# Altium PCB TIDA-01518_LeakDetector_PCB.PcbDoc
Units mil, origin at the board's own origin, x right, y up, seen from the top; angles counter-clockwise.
Board outline 3400 x 1900 mil, 2 copper layers (Top Layer, Bottom Layer), stack 40 mil thick; 53 components, 50 nets, 126 pads, 102 vias.
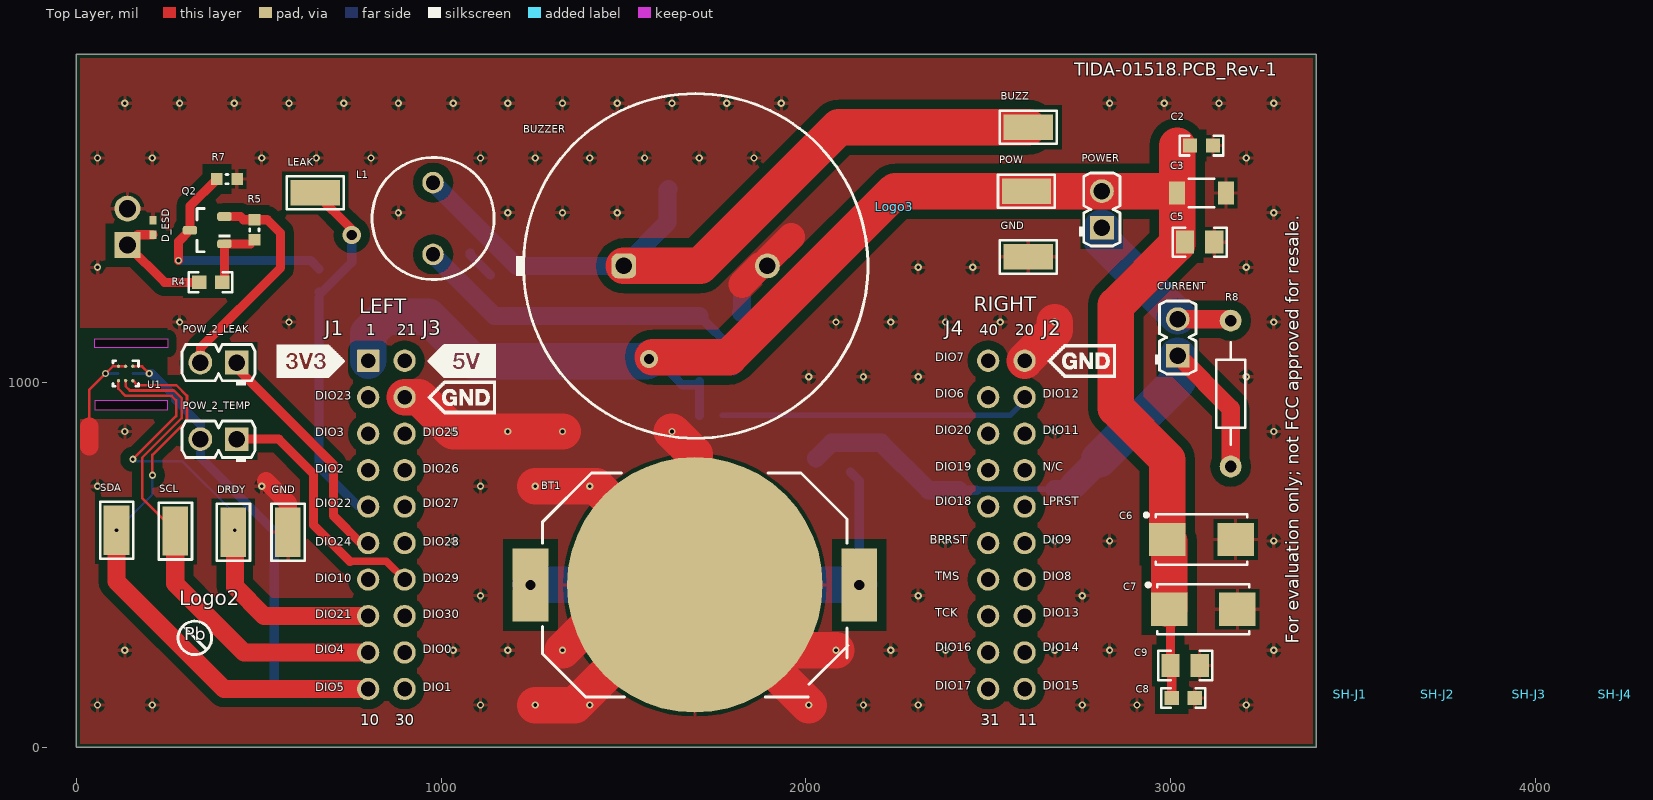
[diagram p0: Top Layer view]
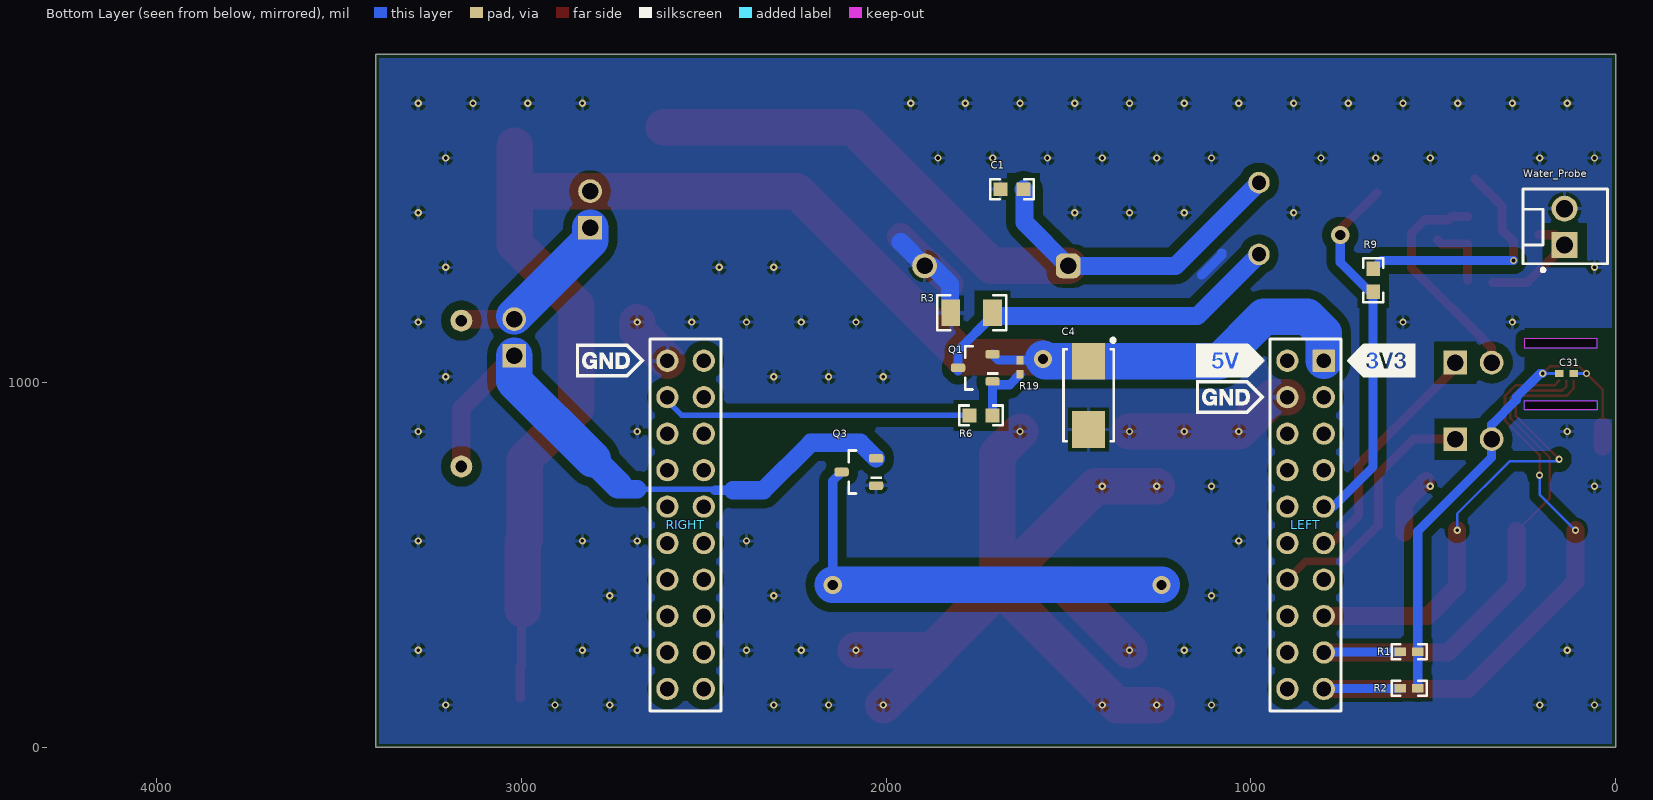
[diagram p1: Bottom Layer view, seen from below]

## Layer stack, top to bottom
Top Solder: solder mask 0.4, Solder Resist, Dk 3.5
Top Layer: signal copper 1.4
Dielectric1: core 37.2, FR-4, Dk 4.8
Bottom Layer: signal copper 1.4
Bottom Solder: solder mask 0.4, Solder Resist, Dk 3.5

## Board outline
0,0 3400,0 3400,1900 0,1900
cut-out: 50,950 50,925 250,925 250,950
cut-out: 50,1095 50,1120 250,1120 250,1095

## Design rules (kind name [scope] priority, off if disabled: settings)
AcuteAngle [All] p1: minimum=4.50000000000000E+0001 checktracksonly=FALSE
AssemblyTestPointUsage [All] p1: valid=2
BoardOutlineClearance BoardOutlineClearance_MountingHoles [OnCopper and InComponentClass('Mounting Holes')] p1: gap=10 ignorepadtopadclearanceinfootprint=FALSE
BoardOutlineClearance BoardOutlineClearance_Poly [OnCopper and IsPoly] p2: gap=10 ignorepadtopadclearanceinfootprint=FALSE
BoardOutlineClearance [OnCopper and Not InComponentClass('Logo') and not InComponentClass('FiducialMark') and not InRegion(1000,500,4000,800) and not InPoly] p3: gap=10 ignorepadtopadclearanceinfootprint=FALSE
Clearance Clearance_Keepouts [((IsTrack Or IsArc) And Not InPoly) And IsFree and IsKeepOut vs ((IsTrack Or IsArc) And Not InPoly) And IsFree and IsKeepOut] p1: gap=0 ignorepadtopadclearanceinfootprint=FALSE
Clearance Clearance_Poly [InPolygon] p2: gap=25 ignorepadtopadclearanceinfootprint=FALSE except(0: Arc-Hole Track-Hole SMDPad-Hole THPad-Hole Via-Hole Fill-Hole Poly-Hole Region-Hole Text-Hole)
Clearance [All] p3: gap=7.87 ignorepadtopadclearanceinfootprint=FALSE except(0: Arc-Hole Track-Hole SMDPad-Hole THPad-Hole Via-Hole Fill-Hole Poly-Hole Region-Hole Text-Hole)
ComponentClearance ComponentClearance_MountingHoles_FiducialMarks [InComponentClass('Mounting Holes') vs InComponentClass('FiducialMark')] p1: gap=50 collisioncheckmode=3 verticalgap=10 showdistances=FALSE
ComponentClearance ComponentClearance_Shunt [InComponentClass('Header') vs InComponentClass('Shunt')] p2: gap=0 collisioncheckmode=3 verticalgap=0 showdistances=FALSE
ComponentClearance ComponentClearance_Logo [InComponentClass('Logo')] p3: gap=50 collisioncheckmode=3 verticalgap=10 showdistances=FALSE
ComponentClearance ComponentClearance_ScrewToNut [(HasFootprint('NY PMS 440 0025 PH')) vs (HasFootprint('Keystone_1902C'))] p4: gap=5 collisioncheckmode=3 verticalgap=10 showdistances=FALSE
ComponentClearance ComponentClearance_MountingHoles [InComponentClass('Mounting Holes')] p5: gap=250 collisioncheckmode=3 verticalgap=100000 showdistances=FALSE
ComponentClearance ComponentClearance_SmallPassives [HasFootprint('0201*') or HasFootprint('0402*') or HasFootprint('0508') or HasFootprint('0603*') or HasFootprint('0612') or HasFootprint('0805*') or HasFootprint('0815*') or HasFootprint('0830*') or HasFootprint('1206*') or HasFootprint('1210*') or HasFootprint('1808*') or HasFootprint('1812*') or HasFootprint('1825*') or HasFootprint('2010*') or HasFootprint('2220*') or HasFootprint('2225*') or HasFootprint('2512*') or HasFootprint('2728*') or HasFootprint('3518*') vs HasFootprint('0201*') or HasFootprint('0402*') or HasFootprint('0508') or HasFootprint('0603*') or HasFootprint('0612') or HasFootprint('0805*') or HasFootprint('0815*') or HasFootprint('0830*') or HasFootprint('1206*') or HasFootprint('1210*') or HasFootprint('1808*') or HasFootprint('1812*') or HasFootprint('1825*') or HasFootprint('2010*') or HasFootprint('2220*') or HasFootprint('2225*') or HasFootprint('2512*') or HasFootprint('2728*') or HasFootprint('3518*')] p6: gap=14.96 collisioncheckmode=3 verticalgap=10 showdistances=FALSE
ComponentClearance ComponentClearance_THtoSMT [IsThruComponent vs IsSMTComponent] p7: gap=40 collisioncheckmode=3 verticalgap=30 showdistances=FALSE
ComponentClearance ComponentClearance_THtoTH [IsThruComponent vs IsThruComponent] p8: gap=30 collisioncheckmode=3 verticalgap=30 showdistances=FALSE
ComponentClearance [All] p9: gap=30 collisioncheckmode=3 verticalgap=10 showdistances=FALSE
DiffPairsRouting [All] p1: maxlimit=100 minlimit=10 mostfreqgap=10 toplayer_minwidth=15 toplayer_maxwidth=15 toplayer_prefwidth=15 bottomlayer_minwidth=15 bottomlayer_maxwidth=15 bottomlayer_prefwidth=15 maxuncoupledlength=1000
FabricationTestPointUsage TestPointUsage [All] p1: valid=2 allowmultiple=FALSE
FabricationTestpoint Testpoint [All] p1: side=3 testpointundercomponent=TRUE minsize=40 maxsize=100 preferedsize=60 minholesize=0 maxholesize=40 preferedholesize=32 testpointgrid=1 allowsidetop=TRUE allowsidebottom=TRUE usegrid=TRUE gridtolerance=0.01
FanoutControl Fanout_LCC [IsLCC] p1: bgadir=Out bgaviamode=Centered fanoutstyle=Auto fanoutdirection=Alternating viagrid=1 // Fanout_LCC (Default Rule)
FanoutControl Fanout_BGA [IsBGA] p2: bgadir=Out bgaviamode=Centered fanoutstyle=Auto fanoutdirection=Alternating viagrid=1 // Fanout_BGA (Default Rule)
FanoutControl Fanout_Default [All] p4: bgadir=Out bgaviamode=Centered fanoutstyle=Auto fanoutdirection=Alternating viagrid=1 // Fanout_Default (Default Rule)
FanoutControl Fanout_Small [(CompPinCount < 5)] p5: bgadir=Out bgaviamode=Centered fanoutstyle=Auto fanoutdirection=OutThenIn viagrid=1 // Fanout_Small (Default Rule)
HoleSize [All] p1: absolutevalues=TRUE maxlimit=251 minlimit=7.87 maxpercent=80.000 minpercent=20.000
MinimumAnnularRing MinimumAnnularRing_ThermalPadVias [IsVia and InAnyComponent] p1: minimumring=5.91
MinimumAnnularRing [All] p2: minimumring=5
MinimumSolderMaskSliver MinimumSolderMaskSliver_Logo [InComponentClass('Logo') vs InComponentClass('Logo')] p1: minsoldermaskwidth=0.7
MinimumSolderMaskSliver [All] p2: minsoldermaskwidth=3.94
PlaneConnect [All] p1: planeconnectstyle=Relief reliefexpansion=10 reliefentries=4 reliefconductorwidth=10 reliefairgap=10
PolygonConnect [All] p1: connectstyle=Relief reliefconductorwidth=10 reliefentries=4 polygonreliefangle="90 Angle" airgapwidth=10
RoutingTopology [All] p1: topology=Daisy_MidDriven
RoutingVias ThermalPadVias [IsVia and InAnyComponent] p1: holewidth=7.87 width=19.68 viastyle="Through Hole" minholewidth=7.87 minwidth=19.68 maxholewidth=12.99 maxwidth=23.62
RoutingVias [All] p2: holewidth=16 width=34 viastyle="Through Hole" minholewidth=5 minwidth=5 maxholewidth=40 maxwidth=65
SilkToBoardRegionClearance [Not ((IsComment or IsDesignator) And (Hide <> 'False')) and not InRegion(1000,500,4000,800)] p1:
SilkToSilkClearance SilkToSilkClearance_Pb-FreeLogo [(HasFootprint('Pb-Free_Overlay_Medium') OR HasFootprint('Pb-Free_Overlay_Small')) vs (HasFootprint('Pb-Free_Overlay_Medium') OR HasFootprint('Pb-Free_Overlay_Small'))] p1: silktosilkclearance=0
SilkToSilkClearance [All] p2: silktosilkclearance=4
SilkToSolderMaskClearance SilkToComponentPadClearance [(IsPad or IsFill or IsRegion) and InAnycomponent] p1: minsilkscreentomaskgap=5 clearancetoexposedcopper=TRUE
SilkToSolderMaskClearance "Silk to Solder Mask Opening" [All] p2: minsilkscreentomaskgap=2.5 clearancetoexposedcopper=FALSE
SolderMaskExpansion [All] p1: expansion=1.97
Width [All] p1: maxlimit=100 minlimit=6 preferedwidth=100 checkconnectedcopper=TRUE
14 further rules are at their usual default settings.

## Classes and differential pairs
component class AssemblyNote: ZZ1 ZZ2 ZZ3 ZZ4
component class BUZZER: BUZZ BUZZER C1 L1 Q1 R3 R6 R19
component class CC1310: C4 LEFT RIGHT
component class HardWare: !PCB Logo2 Logo3 SH-J1 SH-J2 SH-J3 SH-J4 ZZ1 ZZ2 ZZ3 ZZ4
component class Header: CURRENT POW_2_LEAK POW_2_TEMP POWER Water_Probe
component class LeakSensor: D_ESD LEAK POW_2_LEAK Q2 R4 R5 R7 R9 Water_Probe
component class TempSensor: C31 DRDY GND POW_2_TEMP R1 R2 SCL SDA U1
component class TIDA-01518_Main: BT1 C2 C3 C5 C6 C7 C8 C9 CURRENT GND POW POWER Q3 R8
component class Shunt: SH-J1 SH-J2 SH-J3 SH-J4

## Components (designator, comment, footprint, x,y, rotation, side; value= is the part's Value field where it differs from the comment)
BT1 "BAT-HLD-001" LINX_BAT-HLD-001 1698,480 r180 top
BUZZ "5015" Testpoint_Keystone_Miniature 2610,1700 r180 top
BUZZER "CEP-1112" CUI_CEP-1112 1698,1320 r0 top
C1 "06031C472JAT2A" 0603 1655,1530 r0 bottom
C2 "06033C105KAT2A" 0603 3085,1650 r0 top
C3 "C3216X5R1A107M160AC" 1206_190 3085,1520 r0 top
C4 "T495C337K004ATE700" 6032-28 1445,965 r270 bottom
C5 "0805YD106KAT2A" 0805_HV 3080,1385 r0 top
C6 "T495C337K004ATE700" 6032-28 3085,570 r0 top
C7 "T495C337K004ATE700" 6032-28 3090,378.57 r0 top
C8 "06031C103JAT2A" 0603 3035,135.12 r0 top
C9 "GCM21BR71H104KA37K" 0805_HV 3040,224.35 r0 top
C31 "GCM155R71H104KE02D" 0402L 135,1025 r180 bottom
CURRENT "61300211121" WURTH_61300211121 3020,1124 r90 top
D_ESD "TPD1E10B06DPYR" DPY0002A 210,1425 r270 top
DRDY "5015" Testpoint_Keystone_Miniature 430,590 r90 top
GND "5015" Testpoint_Keystone_Miniature 580,590 r90 top
GND "5015" Testpoint_Keystone_Miniature 2610,1345 r0 top
L1 "RLB0913-473K" RLB0913 978,1450 r270 top
LEAK "5015" Testpoint_Keystone_Miniature 655,1520 r180 top
LEFT "SSQ-110-03-T-D" BoosterPack_40pin_J1J3 850,610 r180 bottom
Logo2 "Pb-Free Symbol" Pb-Free_Overlay_Small 325,300 r0 top
Logo3 "FCC disclaimer" FCC_disclaimer 2243,1482 r0 top
POW "5015" Testpoint_Keystone_Miniature 2605,1525 r0 top
POW_2_LEAK "61300211121" WURTH_61300211121 390,1055 r180 top
POW_2_TEMP "61300211121" WURTH_61300211121 390,845 r180 top
POWER "61300211121" WURTH_61300211121 2812,1475 r90 top
Q1 "MMBT2907ALT1G" SOT-23 1755.68,1040.66 r0 bottom
Q2 "MMBT2907ALT1G" SOT-23 358.58,1418 r180 top
Q3 "SI2323DS" SOT-23 2075,755 r0 bottom
R1 "CRCW040210K0FKED" 0402 566.24,261.79 r180 bottom
R2 "CRCW040210K0FKED" 0402 566.24,161.79 r180 bottom
R3 "CRCW1206330RJNEA" 1206 1765.68,1191.69 r180 bottom
R4 "CRCW060320K0JNEA" 0603 368,1275 r0 top
R5 "CRCW0603560KJNEA" 0603L 488,1419 r90 top
R6 "CRCW06035K60JNEA" 0603 1740,910 r180 bottom
R7 "CRCW0603560KJNEA" 0603L 413,1558 r180 top
R8 "CMF5010R200FHEB" CMF50 3165,970 r90 top
R9 "CRCW06030000Z0EA" 0603 665,1280.48 r270 bottom
R19 "CRCW0402330KJNED" 0402L 1633.15,1042.13 r90 bottom
RIGHT "SSQ-110-03-T-D" BoosterPack_40pin_J2J4 2550,610 r180 bottom
SCL "5015" Testpoint_Keystone_Miniature 271,593.01 r90 top
SDA "5015" Testpoint_Keystone_Miniature 110,595 r90 top
SH-J1 "2SN-BK-G" 2SN-BK-G 3493,146 r90 top
SH-J2 "2SN-BK-G" 2SN-BK-G 3733,146 r90 top
SH-J3 "2SN-BK-G" 2SN-BK-G 3983,146 r90 top
SH-J4 "2SN-BK-G" 2SN-BK-G 4220,145 r90 top
U1 "HDC2010YPAR" YPA0006ABAB 135,1025 r270 top
Water_Probe "22-27-2021" MOLEX_22-27-2021 140,1427 r90 bottom
ZZ1 "This Assembly Note is for PCB labels only" AssemblyNoteLabel 185,3938 r0 top
ZZ2 "These assemblies are ESD sensitive, ESD precautions shall be observed." AssemblyNote 185,3829.11 r0 top
ZZ3 "These assemblies must be clean and free from flux and all contaminants. Use of no clean flux is not acceptable." AssemblyNote 185,3740.56 r0 top
ZZ4 "These assemblies must comply with workmanship standards IPC-A-610 Class 2, unless otherwise specified." AssemblyNote 185,3652 r0 top

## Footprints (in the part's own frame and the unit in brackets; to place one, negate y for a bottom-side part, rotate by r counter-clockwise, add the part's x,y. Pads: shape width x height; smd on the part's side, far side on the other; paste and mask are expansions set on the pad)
2SN-BK-G [mil] "Samtec STEP model"
  round 1 on Mech3: 0(0,0)
  body extent -78,-39 79,39, height 188
0402 [mm] "0402 from SM-752 data"
  rect 0.8x0.6 smd: 1(-0.6,0) 2(0.6,0)
  silkscreen extent -1.22,-0.52 1.22,0.52, body extent -0.55,-0.3 0.55,0.3, height 0.6
0402L [mm] "0402 from SM-752 data"
  rect 0.6x0.5 smd: 1(-0.5,0) 2(0.5,0)
  body extent -0.55,-0.3 0.55,0.3, height 0.6
0603 [mm] "0603 from SM-752 data"
  rect 1x0.95 smd: 1(-0.8,0) 2(0.8,0)
  silkscreen extent -1.52,-0.69 1.52,0.69, body extent -0.87,-0.47 0.87,0.47, height 1
0603L [mm] "0603 from SM-752 data"
  rect 0.8x0.85 smd: 1(-0.7,0) 2(0.7,0)
  silkscreen extent -0.07,-0.33 0.07,0.33, body extent -0.87,-0.47 0.87,0.47, height 1
0805_HV [mil] "0805 with 30mil clearance between pads"
  rect 50x63 smd: 1(-40,0) 2(40,0)
  silkscreen extent -74,-40 74,40, body extent -43,-29 43,29, height 57
1206 [mm] "1206 from SM-752 data"
  rect 1.3x1.85 smd: 1(-1.45,0) 2(1.45,0)
  silkscreen extent -2.4,-1.21 2.4,1.21, body extent -1.7,-0.9 1.7,0.9, height 1.35
1206_190 [mm] "1206_190"
  rect 1.1x1.6 smd: 1(-1.7,0) 2(1.7,0)
  silkscreen extent -0.9,-1 0.9,1, body extent -1.75,-0.95 1.75,0.95, height 1.9
6032-28 [mm] "Medium Density IPC based on Vishay Sprague 293D datasheet."
  rect 2.55x2.3 smd: 1(-2.375,0) 2(2.375,0)
  silkscreen extent -3.96,-1.75 3.2,1.82, body extent -3.15,-1.75 3.15,1.75, height 2.8
AssemblyNote [mil] "Assembly Note"
AssemblyNoteLabel [mil] "Assembly Note for PCB Labels"
BoosterPack_40pin_J1J3 [mm] "Receptacle, 2.54mm, 10x2, TH"
  rrect6% 1.55x1.55 hole 1.02: 1(1.27,11.43)
  round 1.55 hole 1.02: 2(1.27,8.89) 3(1.27,6.35) 4(1.27,3.81) 5(1.27,1.27) 6(1.27,-1.27) 7(1.27,-3.81) 8(1.27,-6.35) 9(1.27,-8.89) 10(1.27,-11.43) 21(-1.27,11.43) 22(-1.27,8.89) 23(-1.27,6.35) 24(-1.27,3.81) 25(-1.27,1.27) 26(-1.27,-1.27) 27(-1.27,-3.81) 28(-1.27,-6.35) 29(-1.27,-8.89) 30(-1.27,-11.43)
  silkscreen extent -7.62,-12.95 7.62,12.95, body extent -2.48,-12.95 2.48,12.95, height 8.51
BoosterPack_40pin_J2J4 [mm] "Receptacle, 2.54mm, 10x2, TH"
  round 1.55 hole 1.02: 11(-1.27,-11.43) 12(-1.27,-8.89) 13(-1.27,-6.35) 14(-1.27,-3.81) 15(-1.27,-1.27) 16(-1.27,1.27) 17(-1.27,3.81) 18(-1.27,6.35) 19(-1.27,8.89) 20(-1.27,11.43) 31(1.27,-11.43) 32(1.27,-8.89) 33(1.27,-6.35) 34(1.27,-3.81) 35(1.27,-1.27) 36(1.27,1.27) 37(1.27,3.81) 38(1.27,6.35) 39(1.27,8.89) 40(1.27,11.43)
  silkscreen extent -7.62,-12.95 2.48,12.95, body extent -2.48,-12.95 2.48,12.95, height 8.51
CMF50 [mil] "VIshay Metal Film Resistors 1/4W"
  round 60 hole 32: 1(-200,0) 2(200,0)
  silkscreen extent -140,-40 140,40, body extent -214,-40 214,40, height 80
CUI_CEP-1112 [mm] "TH, 2-Leads, Dia 24mm, Pin Spacing 10mm"
  rrect50% 1.725x1.725 hole 1.15: 1(-5,0)
  round 1.725 hole 1.15: 2(5,0)
  silkscreen extent -12.5,-12 12,12, body extent -12,-12 12,12, height 7.3
DPY0002A [mm] "R-PX2SON-N2"
  rect 0.6x0.5 smd: 1(-0.5,0) 2(0.5,0)
  body extent -0.55,-0.35 0.55,0.35, height 0.4
FCC_disclaimer [mil]
LINX_BAT-HLD-001 [mm] "Linx Technologies"
  round 17.8 smd: 1(0.054,0.883)
  rect 2.5x5.1 smd: 2(-11.396,0.883) 3(11.504,0.883)
  silkscreen extent -10.6,-6.92 10.65,8.68, body extent -10.55,-6.92 10.65,8.68, height 4.31
MOLEX_22-27-2021 [mm] "MOLEX"
  rect 1.8x1.8 hole 1.2: 1(-1.27,0)
  round 1.8 hole 1.2: 2(1.27,0)
  silkscreen extent -3.1,-3 2.63,2.9, body extent -2.51,-3 2.57,2.8, height 11.72
Pb-Free_Overlay_Small [mil]
  silkscreen extent -46,-46 46,46
RLB0913 [mm] "TH, 2-Leads, Dia 8.5mm, Pin Spacing 5mm"
  round 1.5 hole 1: 1(-2.5,0) 2(2.5,0)
  silkscreen extent -4.25,-4.25 4.25,4.25, body extent -5.33,-5.33 5.33,5.33, height 10.16
SOT-23 [mm] "SOT23, 3-Leads, Body 2.9x1.3mm, Pitch 0.95mm, Lead Span 2.5mm, IPC Medium Density"
  rrect50% 1x0.6 smd: 1(-1.2,0.95) 2(-1.2,-0.95) 3(1.2,0)
  silkscreen extent -1.62,-1.5 0.7,1.5, body extent -1.16,-1.45 1.21,1.45, height 1
Testpoint_Keystone_Miniature [mil] "Miniature SMT test point"
  rect 135x70 smd: 1(0,0)
  silkscreen extent -78,-46 78,45, body extent -52,-20 52,20, height 61
WURTH_61300211121 [mm] "Header, 2.54mm, 2x1, TH"
  rect 1.65x1.65 hole 1.15: 1(-1.27,0)
  round 1.65 hole 1.15: 2(1.27,0)
  silkscreen extent -2.54,-1.27 2.54,1.6, body extent -2.54,-1.27 2.54,1.27, height 8.54
YPA0006ABAB [mm] "BGA, 6-Leads, Body1.505x1.505mm, Pitch 0.5mm"
  round 0.23 smd paste-0.13 mask+0.038: A1(-0.5,0.5) A2(0.5,0.5) B1(-0.5,0) B2(0.5,0) C1(-0.5,-0.5) C2(0.5,-0.5)
  silkscreen extent -0.89,-0.89 0.89,0.89, body extent -0.75,-0.75 0.75,0.75, height 0.68

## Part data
BT1: "Battery Holder, Retainer clip, SMT"
BUZZ DRDY GND GND LEAK POW SCL SDA: "Test Point, Miniature, SMT"
BUZZER: library part CMP-0077105-1, "Piezo Audio Transducer, TH"
C1: "CAP, CERM, 4700 pF, 100 V,+/- 5%, X7R, 0603"
C2: "CAP, CERM, 1 µF, 25 V,+/- 10%, X7R, 0603"
C3: "CAP, CERM, 100 µF, 10 V, +/- 20%, X5R, 1206_190"
C4 C6 C7: "CAP, TA, 330 µF, 4 V, +/- 10%, 0.7 ohm, SMD"
C5: "CAP, CERM, 10 µF, 16 V,+/- 10%, X5R, 0805"
C8: "CAP, CERM, 0.01 µF, 100 V,+/- 5%, X7R, 0603"
C9: "CAP, CERM, 0.1 µF, 50 V,+/- 10%, X7R, AEC-Q200 Grade 1, 0805"
C31: "CAP, CERM, 0.1 µF, 50 V,+/- 10%, X7R, AEC-Q200 Grade 1, 0402"
CURRENT POW_2_LEAK POW_2_TEMP POWER: "Header, 2.54 mm, 2x1, Gold, TH"
D_ESD: "ESD in 0402 Package with 10 pF Capacitance and 6 V Breakdown, 1 Channel, -40 to +125 degC, 2-pin X2SON (DPY), Green (RoHS & no Sb/Br)"
L1: library part CMP-0077104-1, "Inductor, Wirewound, Ferrite, 47 mH, .03 A, 99 ohm, TH"
LEFT: library part BoosterPack_40pin_J1J3, "Receptacle, 2.54mm, 10x2, Tin, TH"
Logo2: library part Pb-Free
Logo3: library part FCC_disclaimer, "FCC_disclaimer"
Q1 Q2: library part "MMBT2907ALT1G, ON Semiconductor", "Transistor, PNP, 60 V, 0.6 A, SOT-23"
Q3: "MOSFET, P-CH, -20 V, -3.7 A, SOT-23"
R1 R2: "RES, 10.0 k, 1%, 0.063 W, 0402"
R3: "RES, 330, 5%, 0.25 W, 1206"
R4: "RES, 20 k, 5%, 0.1 W, 0603"
R5 R7: "RES, 560 k, 5%, 0.1 W, 0603"
R6: "RES, 5.6 k, 5%, 0.1 W, 0603"
R8: "RES, 10.2, 1%, 0.25 W, Axial"
R9: "RES, 0, 5%, 0.1 W, 0603"
R19: "RES, 330 k, 5%, 0.063 W, 0402"
RIGHT: library part BoosterPack_40pin_J2J4, "Receptacle, 2.54mm, 10x2, Tin, TH"
SH-J1 SH-J2 SH-J3 SH-J4: "Shunt, 2mm, Gold plated, Black"
U1: "HDC2010 Low Power Humidity and Temperature Digital Sensor, YPA0006ABAB (DSBGA-6)"
Water_Probe: "Header (friction lock), 100mil, 2x1, Tin, TH"
ZZ1: library part AssemblyNoteLabel
ZZ2 ZZ3 ZZ4: library part AssemblyNote

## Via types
v1: diameter 20, hole 10, Top Layer to Bottom Layer, tented both sides, 91 vias
v2: diameter 20, hole 10, Top Layer to Bottom Layer, 7 vias
v3: diameter 50, hole 28, Top Layer to Bottom Layer, 4 vias

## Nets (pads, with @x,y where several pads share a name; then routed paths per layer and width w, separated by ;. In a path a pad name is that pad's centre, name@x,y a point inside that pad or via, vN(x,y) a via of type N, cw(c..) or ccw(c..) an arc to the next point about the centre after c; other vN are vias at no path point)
3V3: C2.1 C3.1 C4.1 C5.1 C6.1 C7.1 C8.1 C9.1 LEFT.1 POW.1 POWER.2 Q1.2 R19.2 | length 4339.8
  Top Layer w25: C7.1 3000,375.07 C9.1 3003.5,220.85 C8.1
  Top Layer w50: C3.1@3013.07,1525 C3.1
  Top Layer w100: v3@1580,1070 1790,1070 2245,1525 POW.1 POWER.2 C3.1@3013.07,1525 ; C7.1 2996.5,565 C6.1 2991.5,788.5 2850,930 2850,1211.93 3018.07,1380 C3.1 3018.07,1650
  Bottom Layer w25: v3(1570,1065) 1573.19,1061.81 R19.2 1692.19,1061.81 Q1.2
  Bottom Layer w100: LEFT.1 800,1135 845,1180 965,1180 1086.5,1058.5 C4.1 1563.5,1058.5 v3(1570,1065)
5V: LEFT.21
"A0/DIO 23": LEFT.2
"A2/ DIO25": LEFT.23
"A3/DIO 26": LEFT.24
"A4/ DIO 27": LEFT.25
A5/DIO28: LEFT.26
"A6/DIO 29": LEFT.27 POW_2_TEMP.1 | length 701.5
  Top Layer w20: 750,510 850,510 LEFT.27
  Top Layer w25: POW_2_TEMP.1 555,845 650,750 650,610 750,510
"A7/DIO 30": LEFT.28
"DIO 0": LEFT.29
"DIO 1": LEFT.30
"DIO 7/ GRN LED": RIGHT.40
"DIO 8/ MISO": RIGHT.14
"DIO 8/ RED LED": RIGHT.39
"DIO 9/MOSI": RIGHT.15
"DIO 11/ SPI CS": RIGHT.18
"DIO 12/ PWM1": R6.1 RIGHT.19 | length 855.1
  Bottom Layer w15: R6.1 2560,910 2600,950 RIGHT.19
"DIO 13/BTN1": RIGHT.13
"DIO 14/BTN2": RIGHT.12
"DIO 15": RIGHT.11
"DIO 18/ RTS /SWO": RIGHT.36
"DIO 19/ CTS": RIGHT.37
"DIO 20/ FLASH CS": RIGHT.38
"DIO 21": DRDY.1 LEFT.8 U1.C2 | length 1354.3
  Top Layer w7: U1.C2 115.32,983.18 135,963.5 261.5,963.5 273.5,951.5 273.5,908.5 v2(155,790)
  Top Layer w50: v2(434.62,595) 434.62,440.38 515,360 LEFT.8
  Bottom Layer w7: v2(155,790) 150,785 290,785 434.62,640.38 v2(434.62,595)
"DIO 22": LEAK.1 LEFT.5 R9.2 | length 999.3
  Top Layer w25: LEAK.1 755,1420 v3(755,1405)
  Bottom Layer w25: R9.2@665,1233.5 665,769.52 774.52,660 LEFT.5 ; R9.2 673.98,1248.98 755,1330 v3(755,1405)
"DIO 24/A1": LEFT.6 POW_2_LEAK.1 | length 655.8
  Top Layer w25: POW_2_LEAK.1 440,1040 705,775 705,635 780,560 LEFT.6
GND: BT1.1 BUZZER.2 C1.2 C2.2 C3.2 C4.2 C5.2 C6.2 C7.2 C8.2 C9.2 C31.2 D_ESD.1 GND.1 LEFT.22 Q3.1 R3.1 R7.1 RIGHT.20 U1.B1 U1.C1 Water_Probe.2 | length 4564.6
  Top Layer w7: 35,880 35,980 v2(80,1025) 99.68,1044.68 U1.C1 U1.B1
  Top Layer w50: 35,825 35,880 ; 520,730 580,670 GND.1@580,590 ; BUZZER.2@1875,1320 BUZZER.2 BUZZER.2@1894.85,1334.85
  Top Layer w75: 1825,1270 BUZZER.2@1875,1320 ; BUZZER.2@1894.85,1334.85 1960,1400
  Top Layer w100: LEFT.22 939,960 v1(1033,866) v1(1183,866) v1(1333,866) ; v1(1258,116) 1366.63,116 BT1.1 ; v1(1258,716) v1(1408,716) 1425.1,716 BT1.1 ; v1(1333,266) 1512.24,445.24 BT1.1 ; v1(1633,866) 1695.87,803.13 BT1.1 ; v1(2008,116) 1695.87,428.13 BT1.1 ; v1(2083,266) 1875.1,266 BT1.1 ; RIGHT.20 2683,1143 v1(2683,1166)
  Bottom Layer w7: v2(80,1025) C31.2
  Bottom Layer w25: 1080,1355 1080,1350 1135,1295
  Bottom Layer w50: R3.1 1825,1193.92 1825,1270 1875,1320 BUZZER.2 1960,1385.15
  other v1: 58,116 208,116 1108,116 1408,116 2158,116 2308,116 2758,116 2908,116 3208,116 133,266 1033,266 1183,266 2233,266 2383,266 2683,266 2833,266 3283,266 1108,416 2308,416 2758,416 1033,566 2383,566 2683,566 2833,566 3283,566 58,716 508,716 1108,716 133,866 2683,866 3283,866 2008,1016 2158,1016 2308,1016 3208,1016 283,1166 583,1166 2083,1166 2233,1166 2383,1166 2533,1166 3283,1166 58,1316 2308,1316 2458,1316 3208,1316 883,1466 1183,1466 1333,1466 1483,1466 3283,1466 58,1616 208,1616 508,1616 658,1616 808,1616 1108,1616 1258,1616 1408,1616 1558,1616 1708,1616 1858,1616 3208,1616 133,1766 283,1766 433,1766 583,1766 733,1766 883,1766 1033,1766 1183,1766 1333,1766 1483,1766 1633,1766 1783,1766 1933,1766 2833,1766 2983,1766 3133,1766 3283,1766
"I2C SCL/ DIO 4": LEFT.9 R1.1 SCL.1 U1.B2 | length 1591.5
  Top Layer w7: U1.B2 135,990 146.63,978.37 267.66,978.37 288.37,957.66 288.37,902.34 180,793.97 180,684.01 SCL.1
  Top Layer w50: SCL.1 271,449 460,260 LEFT.9
  Bottom Layer w25: R1.1 798.21,261.79 LEFT.9
"I2C_SDA/DIO 5": LEFT.10 R2.1 SDA.1 U1.A2 | length 1777.7
  Top Layer w7: U1.A2 166.75,993.25 273.82,993.25 303.25,963.82 303.25,896.18 208.62,801.55 v2(208.62,746.38)
  Top Layer w50: v2(110,595) 110,455 405,160 LEFT.10
  Bottom Layer w7: v2(110,595) 208.62,693.62 v2(208.62,746.38)
  Bottom Layer w25: R2.1 798.21,161.79 LEFT.10
"LP RST": RIGHT.16
N/C: RIGHT.17
NetBUZZ_1: BUZZ.1 BUZZER.1 C1.1 L1.1 | length 2144.7
  Top Layer w100: BUZZER.1 1710,1320 2090,1700 BUZZ.1
  Bottom Layer w50: L1.1 1206.43,1320 BUZZER.1 1620.91,1439.76 1620.91,1527.41 C1.1
NetC31_1: C31.1 POW_2_TEMP.2 R1.2 R2.2 U1.A1 | length 1107.9
  Top Layer w7: U1.A1 180.32,1044.68 v2(200,1025)
  Bottom Layer w7: C31.1 175,1025 v2(200,1025)
  Bottom Layer w25: v2(200,1025) 206.82,1025 272.5,959.32 272.5,952.5 340,885 POW_2_TEMP.2 340,795 542.62,592.38 R1.2 R2.2
NetCURRENT_1: CURRENT.1 Q3.2 R8.1 | length 1599.8
  Top Layer w50: CURRENT.1 3165,929 R8.1
  Bottom Layer w15: 2472.87,707.87 2682.87,707.87
  Bottom Layer w25: 2420,705 2470,705
  Bottom Layer w50: Q3.2 2070.35,835 2206.69,835 2336.69,705 2420,705 ; 2682.87,707.87 2722.87,707.87
  Bottom Layer w75: 2735,720 2805,790
  Bottom Layer w100: 2805,790 3020,1005 CURRENT.1
NetCURRENT_2: CURRENT.2 POWER.1 R8.2 | length 485.8
  Top Layer w50: CURRENT.2 3161,1174 R8.2
  Bottom Layer w50: POWER.1@2805,1418 POWER.1
  Bottom Layer w100: POWER.1 2812,1389.87 CURRENT.2@3020,1181.87
NetD_ESD_2: D_ESD.2 R4.1 Water_Probe.1 | length 320.5
  Top Layer w25: D_ESD.2 168.32,1405.32 Water_Probe.1 242,1275 R4.1
NetL1_2: L1.2 Q1.3 R3.2 | length 990.6
  Bottom Layer w25: R3.2@1708.59,1182.7 1802.92,1088.37 Q1.3 Q1.3@1802.92,1031.67
  Bottom Layer w50: L1.2 1146.88,1182.7 R3.2@1708.59,1182.7
NetPOW_2_LEAK_2: POW_2_LEAK.2 Q2.2 R5.2 | length 619.1
  Top Layer w25: POW_2_LEAK.2 340,1095 560,1315 560,1410 523.44,1446.56 R5.2 458.44,1446.56 449.6,1455.4 Q2.2
NetQ1_1: Q1.1 R6.2 R19.1 | length 180.2
  Bottom Layer w25: R19.1 1661.32,994.27 Q1.1@1708.43,994.27 ; Q1.1 Q1.1@1708.43,994.27 ; R6.2 1708.43,910.07 Q1.1@1708.43,994.27
NetQ2_1: Q2.1 R4.2 R5.1 | length 194.9
  Top Layer w10: R4.2 R4.2@405.82,1281.33
  Top Layer w25: R4.2@405.82,1281.33 Q2.1 477.16,1380.6 R5.1
NetQ2_3: Q2.3 R7.2 R9.1 | length 661.2
  Top Layer w25: v2(280,1335) 280,1386.66 Q2.3 311.34,1483.9 R7.2
  Bottom Layer w25: v2(280,1335) 641.98,1335 R9.1
RESET: RIGHT.35
"RXD/DIO 2": LEFT.4
"SPI CLK/DIO 10": LEFT.7
TCK: RIGHT.33
TDI: RIGHT.31
TDO: RIGHT.32
TMS: RIGHT.34
"TXD/DIO 3": LEFT.3
V+: BT1.2 BT1.3 Q3.3 | length 1238.3
  Top Layer w50: v3(2146.65,445.24) BT1.2@2163.54,445.24
  Bottom Layer w25: Q3.3 2146.65,730.59 v3(2146.65,445.24)
  Bottom Layer w100: v3(1245.08,445.24) v3(2146.65,445.24)
pads on no net: SH-J1.0 SH-J2.0 SH-J3.0 SH-J4.0

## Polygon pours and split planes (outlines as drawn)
no net on Bottom Layer "BOTTOM_LAYER_NONET_P006" (solid, remove dead copper, pour order 6): 50,950 250,950 250,925 50,925 50,940
no net on Bottom Layer "BOTTOM_LAYER_NONET_P004" (solid, remove dead copper, pour order 4): 50,1120 250,1120 250,1095 50,1095 50,1110
GND on Bottom Layer "BOTTOM_LAYER_GND_P000" (solid, remove dead copper, pour order 0): 0,1900 3400,1900 3400,0 0,0
GND on Top Layer "TOP_LAYER_GND_P002" (solid, remove dead copper, pour order 2): 0,1900 3400,1900 3400,0 0,0

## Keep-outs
Keep-Out Layer:
  text ".Layer_Name" at 577,-858.49 h20

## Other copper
Top Layer:
  pour cut-out: 0,1150 250,1150 250,900 0,900
  text ".Layer_Name" at 577,-858.49 h20
Bottom Layer:
  pour cut-out: 0,1150 250,1150 250,900 0,900
  text ".Layer_Name" at 577,-858.49 h20

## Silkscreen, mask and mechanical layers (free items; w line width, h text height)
Top Overlay:
  text "TIDA-01518.PCB_Rev-1" at 2736,1829 h60
  text "DIO7" at 2355,1050 h40
  text "DIO6" at 2355,950 h40
  text "DIO12" at 2650,950 h40
  text "DIO23" at 655,945 h40
  text "DIO20" at 2355,850 h40
  text "DIO11" at 2650,850 h40
  text "DIO3" at 655,845 h40
  text "DIO25" at 950,845 h40
  text "DIO19" at 2355,750 h40
  text "N/C" at 2650,750 h40
  text "DIO2" at 655,745 h40
  text "DIO26" at 950,745 h40
  text "DIO18" at 2355,655 h40
  text "LPRST" at 2650,655 h40
  text "DIO22" at 655,650 h40
  text "DIO27" at 950,650 h40
  text "BPRST" at 2340,550 h40
  text "DIO9" at 2650,550 h40
  text "DIO24" at 655,545 h40
  text "DIO28" at 950,545 h40
  text "TMS" at 2355,450 h40
  text "DIO8" at 2650,450 h40
  text "DIO10" at 655,445 h40
  text "DIO29" at 950,445 h40
  text "TCK" at 2355,350 h40
  text "DIO13" at 2650,350 h40
  text "DIO21" at 655,345 h40
  text "DIO30" at 950,345 h40
  text "DIO16" at 2355,255 h40
  text "DIO14" at 2650,255 h40
  text "DIO4" at 655,250 h40
  text "DIO0" at 950,250 h40
  text "DIO17" at 2355,150 h40
  text "DIO15" at 2650,150 h40
  text "DIO5" at 655,145 h40
  text "DIO1" at 950,145 h40
  text ".Layer_Name" at 577,-858.49 h20
Bottom Overlay:
  text ".Layer_Name" at 577,-858.49 h20
Top Paste:
  text ".Layer_Name" at 577,-858.49 h20
Bottom Paste:
  text ".Layer_Name" at 577,-858.49 h20
Top Solder:
  text ".Layer_Name" at 577,-858.49 h20
  text ".Layer_Name" at 577,-858.49 h20
Bottom Solder:
  text ".Layer_Name" at 577,-858.49 h20
Drill Guide:
  text ".Layer_Name" at 577,-858.49 h20
M1 Board Outline:
  the board outline again, w10
  text ".Layer_Name" at 577,-858.49 h20
M2 Board Dimensions:
  rectangle: 0,-275 125,-150
  rectangle: 125,-400 500,-275
  lines w7: 0,-275 1000,-275 ; 125,-400 125,-150 ; 250,-400 250,-150 ; 500,-400 500,-150 ; 750,-400 750,-150 ; 0,-400 1000,-400 1000,-150 0,-150 0,-400
  text ".Layer_Name" at 577,-858.49 h20
M3 3D STEP Top:
  text ".Layer_Name" at 577,-858.49 h20
M4 3D STEP Bottom:
  text ".Layer_Name" at 577,-858.49 h20
M5 Assembly Top:
  lines w10: -292,-930.17 6308,-930.17 ; -292,-726.83 6310,-726.83 ; -292,-523.5 -292,-1133.5 3713,-1133.5 6310,-1133.5 6310,-523.5 -291.5,-523.5 -291.5,-1133.5 1284,-1133.5 ; 2173,-1133.5 2173,-523.5 ; 3440,-726.83 3440,-523.5 ; 4280,-726.83 4280,-523.5 ; 4902,-1140 4902,-937.17
  text "COMPONENTS MARKED 'DNP' SHOULD NOT BE POPULATED." at 1153.5,-318.5 h20
  text "ASSEMBLY VARIANT:" at 1153,-434 h20
  text ".VariantName" at 2189,-434 h20
  text "PCB VIEWED FROM TOP SIDE" at -228.5,-655.67 h20
  text "BOARD #:" at 2248,-655.67 h20
  text ".PRJ_Number" at 2793.5,-655.67 h20
  text "REV:" at 3638,-655.67 h20
  text ".PCB_Rev" at 3929.5,-655.67 h20
  text "SVN REV:" at 4476,-655.67 h20
  text ".VersionControl_RevNumber" at 4982,-655.67 h20
  text "TID #:" at 2248,-859 h20
  text ".TID" at 2793.5,-859 h20
  text "PLOT NAME =" at -228.5,-1064.34 h20
  text ".plot_File_Name" at 577,-1064.34 h20
  text "GENERATED    :" at 2250,-1064.34 h20
  text ".Print_Date" at 3119.5,-1064.34 h20
  text ".Print_Time" at 3848.5,-1064.34 h20
  text "TEXAS INSTRUMENTS" at 5113,-1064.34 h20
M6 Assembly Bottom:
  lines w10: -292.5,-727.33 6309.5,-727.33 ; -290.5,-930.67 6309.5,-930.67 ; 1115.5,-1140.5 1115.5,-937.67 ; 1737.5,-727.33 1737.5,-524 ; 2577.5,-727.33 2577.5,-524 ; 3844.5,-1134 3844.5,-524 ; 4733.5,-1134 6309,-1134 6309,-524 -292.5,-524 -292.5,-1134 2304.5,-1134 6309.5,-1134 6309.5,-524
  text "COMPONENTS MARKED 'DNP' SHOULD NOT BE POPULATED." at 6102,-318 h20
  text ".VariantName" at 5058,-434 h20
  text "ASSEMBLY VARIANT:" at 6097,-434 h20
  text ".VersionControl_RevNumber" at 1035.5,-656.17 h20
  text "SVN REV:" at 1541.5,-656.17 h20
  text ".PCB_Rev" at 2088,-656.17 h20
  text "REV:" at 2379.5,-656.17 h20
  text ".PRJ_Number" at 3224,-656.17 h20
  text "BOARD #:" at 3769.5,-656.17 h20
  text "PCB VIEWED FROM BOTTOM SIDE" at 6246,-656.17 h20
  text ".TID" at 3224,-859.5 h20
  text "TID #:" at 3769.5,-859.5 h20
  text "TEXAS INSTRUMENTS" at 904.5,-1064.84 h20
  text ".Print_Time" at 2169,-1064.84 h20
  text ".Print_Date" at 2898,-1064.84 h20
  text "GENERATED    :" at 3767.5,-1064.84 h20
  text ".plot_File_Name" at 5440.5,-1064.84 h20
  text "PLOT NAME =" at 6246,-1064.84 h20
M9 Title Sheet:
  drawing of 57 lines, arcs and shapes, not listed
  text "1" at 739.84,8036.5 h20
  text "2" at 3235.5,8036.5 h20
  text "3" at 5724.84,8036.5 h20
  text "4" at 8231.51,8036.5 h20
  text "5" at 10730.5,8036.5 h20
  text "6" at 13235.5,8036.5 h20
  text "A" at -416.5,6893.5 h20
  text "A" at 14383.5,6893.5 h20
  text "B" at -416.5,4513.5 h20
  text "B" at 14383.5,4513.5 h20
  text "C" at -416.5,2138.5 h20
  text "C" at 14383.5,2138.5 h20
  text "PROJECT TITLE:" at 11343.5,277.5 h20
  text ".PRJ_Title" at 11393.5,144.17 h20
  text "DESIGNED FOR:" at 11343.5,-23.5 h20
  text ".PRJ_Customer" at 11393.5,-163.5 h20
  text "D" at -416.5,-231.5 h20
  text "D" at 14383.5,-231.5 h20
  text "FILE NAME:" at 11343.5,-323.5 h20
  text ".PCB_File_Name_No_Path" at 11393.5,-443.5 h20
  text "Texas Instruments (TI) and/or its licensors do not warrant the accuracy or completeness of this specification" at 6374,-605.34 h20
  text "ENGINEER:" at 11343.5,-613.5 h20
  text "LAYOUT BY:" at 12848.5,-613.5 h20
  text "or any information contained therein. TI and/or its licensors do not warrant that this design will meet" at 6329.01,-718 h20
  text ".PRJ_Engineer" at 11393.5,-768.49 h20
  text ".PCB_Layout" at 12899,-768.49 h20
  text "the specifications, will be suitable for your application or fit for any particular purpose, or will operate in" at 6329.01,-830.67 h20
  text ".Layer_Name" at 577,-858.49 h20
  text "ALTIUM DESIGNER VERSION:" at 12848.5,-923.5 h20
  text "an implementation. TI and/or its licensors do not warrant that the design is production worthy. You should" at 6329.01,-943.33 h20
  text "completely validate and test your design implementation to confirm the system functionality for your application." at 6374,-1056 h20
  text ".print_Scale" at 11393.5,-1056.83 h20
  text ".Application_BuildNumber" at 12899,-1056.83 h20
  text "1" at 739.84,-1263.5 h20
  text "2" at 3235.5,-1263.5 h20
  text "3" at 5724.84,-1263.5 h20
  text "4" at 8231.51,-1263.5 h20
  text "5" at 10730.5,-1263.5 h20
  text "6" at 13235.5,-1263.5 h20
M10 Fab Notes:
  drawing of 173 lines, arcs and shapes, not listed
  text "DESIGN INFORMATION" at 12378.02,6201 h20
  text "MIN. TRACK WIDTH:" at 11733.46,6021 h20
  text "8" at 12829.7,6021 h20
  text "MIL" at 12984.46,6021 h20
  text "MIN. CLEARANCE:" at 11733.46,5889 h20
  text "0.2" at 12769.7,5889 h20
  text "mm" at 12984.46,5889 h20
  text "MIN. VIA PAD SIZE:" at 11733.46,5757 h20
  text "24" at 12799.71,5757 h20
  text "MIL" at 12984.46,5757 h20
  text "0.05mm (2MIL)" at 12428.46,5615.29 h20
  text "MINIMUM ANNULAR RING" at 11404.23,5611 h20
  text "EXTERNAL" at 13136.46,5611 h20
  text "PER" at 11604.23,5493 h20
  text "IPC-D-275 CLASS 2 LEVEL C" at 11824.23,5493 h20
  text "MIL, HOLES" at 13312.46,5380.71 h20
  text "+/-" at 12920,5380 h20
  text "+/-" at 13774,5380 h20
  text "REGISTRATION TOLERANCES:" at 11404.23,5375 h20
  text "METAL" at 12604,5375 h20
  text "5" at 13180.2,5375 h20
  text "3" at 14013.2,5375 h20
  text "MIL" at 14129.46,5375 h20
  text "+/-" at 13774,5262 h20
  text "HOLE SIZE TOLERANCE (UNLESS OTHERWISE SPECIFIED):" at 11404.23,5257 h20
  text "3" at 14013.2,5257 h20
  text "MIL" at 14129.46,5257 h20
  text "MATERIAL:" at 11329.46,5047.54 h20
  text "FR-4 High Tg" at 12315.9,4907.21 h20
  text "FR-408" at 11750.46,4898.64 h20
  text "OTHER" at 13238.46,4898.64 h20
  text "X" at 12161,4895 h20
  text "62 MIL (1.6mm) +/-10%" at 12070.56,4735.92 h20
  text "THICKNESS:" at 11404.23,4731.64 h20
  text "X" at 11942.4,4731.64 h20
  text "OTHER" at 13355.46,4731.64 h20
  text "TOLERANCE:" at 11404.23,4573.64 h20
  text "X" at 12243.53,4573.64 h20
  text "ANSI IPC-6012 TYPE 3 CLASS 2" at 12430.48,4573.64 h20
  text "OTHER +/-" at 12430.46,4417.64 h20
  text "BOW & TWIST:" at 11404.23,4260.64 h20
  text "X" at 12243.53,4260.64 h20
  text "ANSI IPC-6012 TYPE 3 CLASS 2" at 12430.48,4260.64 h20
  text "OTHER +/-" at 12430.46,4102.13 h20
  text "DRILLING:" at 11329.46,3963.64 h20
  text "REFERENCE:" at 11404.23,3846.64 h20
  text "X" at 12052.46,3846.64 h20
  text "AS SHOWN" at 12239.46,3846.64 h20
  text "X" at 12953.46,3846.64 h20
  text "NC_DRILL FILES" at 13090.46,3846.64 h20
  text "PTH COPPER THICKNESS:" at 11404.23,3688.64 h20
  text "X" at 12534.46,3688.64 h20
  text "20-30 um" at 12671.46,3688.64 h20
  text "OTHER" at 13388.46,3688.64 h20
  text "BOARD FINISH:" at 11329.46,3529.64 h20
  text "SILKSCREEN:" at 11484.68,3411.64 h20
  text "X" at 12433.46,3411.64 h20
  text "TOP" at 12559.46,3411.64 h20
  text "X" at 12943.46,3411.64 h20
  text "BOTTOM" at 13070.46,3411.64 h20
  text "SILKSCREEN COLOR:" at 11484.68,3244.64 h20
  text "X" at 12432.42,3244.64 h20
  text "WHITE" at 12559.46,3244.64 h20
  text "OTHER" at 13070.46,3244.64 h20
  text "X" at 12563.42,3085.44 h20
  text "GREEN" at 12690.46,3085.44 h20
  text "OTHER" at 13308.46,3085.44 h20
  text "SOLDER RESIST COLOR:" at 11484.68,3074.64 h20
  text "X" at 12563.42,2915.44 h20
  text "MATTE" at 12690.46,2915.44 h20
  text "SEMI-GLOSS" at 13308,2914.8 h20
  text "IMMERSION GOLD (ENIG)" at 12390.46,2726.92 h20
  text "ENEPIG" at 13728,2723.64 h20
  text "SURFACE FINISH:" at 11329.46,2722.64 h20
  text "X" at 12203.51,2722.64 h20
  text "IMM. TIN/SILVER OR EQUIV" at 11659,2565.64 h20
  text "OTHER" at 13090.46,2565.64 h20
  text "ARRAY/PANEL:" at 11329.46,2386.64 h20
  text "CUT AND TRIM PER M1 BOARD OUTLINE" at 12390.46,2382.35 h20
  text "N.C. ROUTE" at 12390.46,2230.64 h20
  text "X" at 13069.46,2230.64 h20
  text "V. SCORE" at 13256.46,2230.64 h20
  text "CERTIFICATION:" at 11329.46,2093.64 h20
  text "MATERIALS AND WORKMANSHIP FOR ALL PCBS" at 12054.46,2093.64 h20
  text "TO MEET OR EXCEED THE REQUIREMENTS OF:" at 12054.46,1995.64 h20
  text "X" at 11680.96,1859.13 h20
  text "ANSI IPC-A-600F CLASS ->" at 11819.96,1859.13 h20
  text "X" at 13459.02,1859.13 h20
  text "2" at 13577.96,1859.14 h20
  text "1" at 13262.96,1857.64 h20
  text "3" at 13931.96,1857.64 h20
  text "X" at 12495.02,1699.64 h20
  text "RoHS" at 12631.96,1699.64 h20
  text "OTHER" at 13276.36,1699.64 h20
  text "PER ORDER" at 13673.42,1699.64 h20
  text "ALL BOARDS MUST MEET OR EXCEED UL94-V0 REQUIREMENTS." at 11357,1534 h20
  text "PCB MUST BEAR THE UL94V-0 UL REGISTERED MATERIAL ID NUMBER" at 11357,1414 h20
  text "ADDITIONAL REQUIREMENTS:" at 11329.46,1240.64 h20
  text "MICROSECTION:" at 11404.23,1125.64 h20
  text "YES" at 12309.96,1125.64 h20
  text "REQUIRED" at 13171.46,969.49 h20
  text "BARE BOARD ELEC. TEST:" at 11404.23,966.64 h20
  text "NONE" at 12709.96,966.64 h20
  text "X" at 13044.46,966.64 h20
  text "PER ORDER" at 13763.46,966.64 h20
  text ".Layer_Name" at 577,-858.49 h20
M11 Gerber Information:
  lines w10: -292,-930.17 6308,-930.17 ; -292,-726.83 6310,-726.83 ; -292,-523.5 -292,-1133.5 3713,-1133.5 6310,-1133.5 6310,-523.5 -291.5,-523.5 -291.5,-1133.5 1284,-1133.5 ; 2173,-1133.5 2173,-523.5 ; 3440,-726.83 3440,-523.5 ; 4280,-726.83 4280,-523.5 ; 4902,-1140 4902,-937.17
  text "ALL ARTWORK VIEWED FROM TOP SIDE" at -228.5,-655.67 h20
  text "BOARD #:" at 2248,-655.67 h20
  text ".PRJ_Number" at 2793.5,-655.67 h20
  text "REV:" at 3638,-655.67 h20
  text ".PCB_Rev" at 3929.5,-655.67 h20
  text "SVN REV:" at 4476,-655.67 h20
  text ".VersionControl_RevNumber" at 4982,-655.67 h20
  text "LAYER NAME =" at -228.5,-858.49 h20
  text "TID #:" at 2248,-859 h20
  text ".TID" at 2793.5,-859 h20
  text "PLOT NAME =" at -228.5,-1064.34 h20
  text ".plot_File_Name" at 577,-1064.34 h20
  text "GENERATED    :" at 2250,-1064.34 h20
  text ".Print_Date" at 3119.5,-1064.34 h20
  text ".Print_Time" at 3848.5,-1064.34 h20
  text "TEXAS INSTRUMENTS" at 5113,-1064.34 h20
M12 Stackup:
  drawing of 198 lines, arcs and shapes, not listed
  text "Layer" at 9757.84,7910 h20
  text "Name" at 9907.81,7910 h20
  text "Material" at 10231.06,7910 h20
  text "Thickness" at 10530.98,7910 h20
  text "Constant" at 10760.93,7910 h20
  text "Board Layer Stack" at 10964.22,7910 h20
  text "1" at 9757.84,7870 h20
  text "Top Overlay" at 9907.81,7870 h20
  text "2" at 9757.84,7830 h20
  text "Top Solder" at 9907.81,7830 h20
  text "Solder Resist" at 10231.06,7830 h20
  text "0.40mil" at 10530.98,7830 h20
  text "3.5" at 10760.93,7830 h20
  text "3" at 9757.84,7790 h20
  text "Top Layer" at 9907.81,7790 h20
  text "Copper" at 10231.06,7790 h20
  text "1.40mil" at 10530.98,7790 h20
  text "4" at 9757.84,7750 h20
  text "Dielectric1" at 9907.81,7750 h20
  text "FR-4" at 10231.06,7750 h20
  text "59.20mil" at 10530.98,7750 h20
  text "4.8" at 10760.93,7750 h20
  text "5" at 9757.84,7710 h20
  text "Bottom Layer" at 9907.81,7710 h20
  text "Copper" at 10231.06,7710 h20
  text "1.40mil" at 10530.98,7710 h20
  text "6" at 9757.84,7670 h20
  text "Bottom Solder" at 9907.81,7670 h20
  text "Solder Resist" at 10231.06,7670 h20
  text "0.40mil" at 10530.98,7670 h20
  text "3.5" at 10760.93,7670 h20
  text "7" at 9757.84,7630 h20
  text "Bottom Overlay" at 9907.81,7630 h20
  text ".Layer_Name" at 577,-858.49 h20
M13 Component Bodies Top:
  text ".Layer_Name" at 577,-858.49 h20
M14 Component Bodies Bottom:
  text ".Layer_Name" at 577,-858.49 h20
M15 Courtyards Top:
  text ".Layer_Name" at 577,-858.49 h20
M16 Courtyards Bottom:
  text ".Layer_Name" at 577,-858.49 h20
Drill Drawing:
  circle w10: c3873.72,1596.96 r27.63
  lines w10: 3846.09,947.74 3901.34,947.74 3901.34,1002.99 3846.09,1002.99 3846.09,947.74 ; 3846.09,1085.87 3859.9,1085.87 3873.72,1072.06 3887.53,1085.87 3901.34,1085.87 3887.53,1099.68 3901.34,1113.5 3887.53,1113.5 3873.72,1127.31 3859.9,1113.5 3846.09,1113.5 3859.9,1099.68 3846.09,1085.87 ; 3846.09,1224 3873.72,1196.38 3901.34,1224 3873.72,1251.63 3846.09,1224 ; 3846.09,1320.7 3873.72,1334.51 3901.34,1320.7 3887.53,1348.32 3901.34,1375.95 3873.72,1362.14 3846.09,1375.95 3859.9,1348.32 3846.09,1320.7 ; 3846.09,1458.83 3859.9,1458.83 3859.9,1445.02 3887.53,1445.02 3887.53,1458.83 3901.34,1458.83 3901.34,1486.46 3887.53,1486.46 3887.53,1500.27 3859.9,1500.27 3859.9,1486.46 3846.09,1486.46 3846.09,1458.83 ; 3846.09,1693.66 3846.09,1707.47 3859.9,1721.28 3846.09,1735.1 3846.09,1748.91 3859.9,1748.91 3873.72,1735.1 3887.53,1748.91 3901.34,1748.91 3901.34,1735.1 3887.53,1721.28 3901.34,1707.47 3901.34,1693.66 3887.53,1693.66 3873.72,1707.47 3859.9,1693.66 3846.09,1693.66
  lines w12: 3796,910.44 7027.49,910.44 ; 3796,1780.68 7027.49,1780.68 ; 4133.86,786.12 4133.86,1905 ; 4465.86,786.12 4465.86,1905 ; 5102.43,786.12 5102.43,1905 ; 5361.57,786.12 5361.57,1905 ; 5736.72,786.12 5736.72,1905 ; 6461.05,786.12 6461.05,1905 ; 3796,786.12 7027.49,786.12 7027.49,1905 3796,1905 3796,786.12
  text "Symbol" at 3870.59,1817.98 h72
  text "Quantity" at 4171.16,1817.98 h72
  text "Finished Hole Size" at 4503.16,1817.98 h72
  text "Plated" at 5139.72,1817.98 h72
  text "Hole Type" at 5398.86,1817.98 h72
  text "Drill Layer Pair" at 5774.02,1817.98 h72
  text "Hole Tolerance" at 6498.35,1817.98 h72
  text "98" at 4171.16,1693.66 h60
  text "10.00mil (0.254mm)" at 4503.16,1693.66 h60
  text "PTH" at 5139.72,1693.66 h60
  text "Round" at 5398.86,1693.66 h60
  text "Top Layer - Bottom Layer" at 5774.02,1693.66 h60
  text "4" at 4171.16,1569.34 h60
  text "28.00mil (0.711mm)" at 4503.16,1569.34 h60
  text "PTH" at 5139.72,1569.34 h60
  text "Round" at 5398.86,1569.34 h60
  text "Top Layer - Bottom Layer" at 5774.02,1569.34 h60
  text "2" at 4171.16,1445.02 h60
  text "32.00mil (0.813mm)" at 4503.16,1445.02 h60
  text "PTH" at 5139.72,1445.02 h60
  text "Round" at 5398.86,1445.02 h60
  text "Top Layer - Bottom Layer" at 5774.02,1445.02 h60
  text "2" at 4171.16,1320.7 h60
  text "39.37mil (1.000mm)" at 4503.16,1320.7 h60
  text "PTH" at 5139.72,1320.7 h60
  text "Round" at 5398.86,1320.7 h60
  text "Top Layer - Bottom Layer" at 5774.02,1320.7 h60
  text "40" at 4171.16,1196.38 h60
  text "40.16mil (1.020mm)" at 4503.16,1196.38 h60
  text "PTH" at 5139.72,1196.38 h60
  text "Round" at 5398.86,1196.38 h60
  text "Top Layer - Bottom Layer" at 5774.02,1196.38 h60
  text "10" at 4171.16,1072.06 h60
  text "45.28mil (1.150mm)" at 4503.16,1072.06 h60
  text "PTH" at 5139.72,1072.06 h60
  text "Round" at 5398.86,1072.06 h60
  text "Top Layer - Bottom Layer" at 5774.02,1072.06 h60
  text "2" at 4171.16,947.74 h60
  text "47.24mil (1.200mm)" at 4503.16,947.74 h60
  text "PTH" at 5139.72,947.74 h60
  text "Round" at 5398.86,947.74 h60
  text "Top Layer - Bottom Layer" at 5774.02,947.74 h60
  text "158 Total" at 4171.16,823.42 h60
  text ".Layer_Name" at 577,-858.49 h20
Mechanical 17:
  text ".Layer_Name" at 577,-858.49 h20
Mechanical 18:
  text ".Layer_Name" at 577,-858.49 h20
Mechanical 19:
  text ".Layer_Name" at 577,-858.49 h20

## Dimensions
0,-400 to 1000,-400 on M2 Board Dimensions
0,0 to 0,1900 on M2 Board Dimensions
0,0 to 3400,0 on M2 Board Dimensions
